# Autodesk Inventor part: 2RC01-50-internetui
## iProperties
Created: 2010-11
Part Number: 2RC01-50-internetui
Document SubType Name: Modeling
Designer: Darius
Author: Darius
Translation Standard: STEP AP203
File Name: 2RC01-50.STEP
Preprocessor: SolidWorks 2003240
Postprocessor: Build: 272, Release: 10 SP3a - Date: Thu 12/15/2005
Sent Units: MILLIMETERS
Uncertainty: 1e-05
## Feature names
1. Base1
